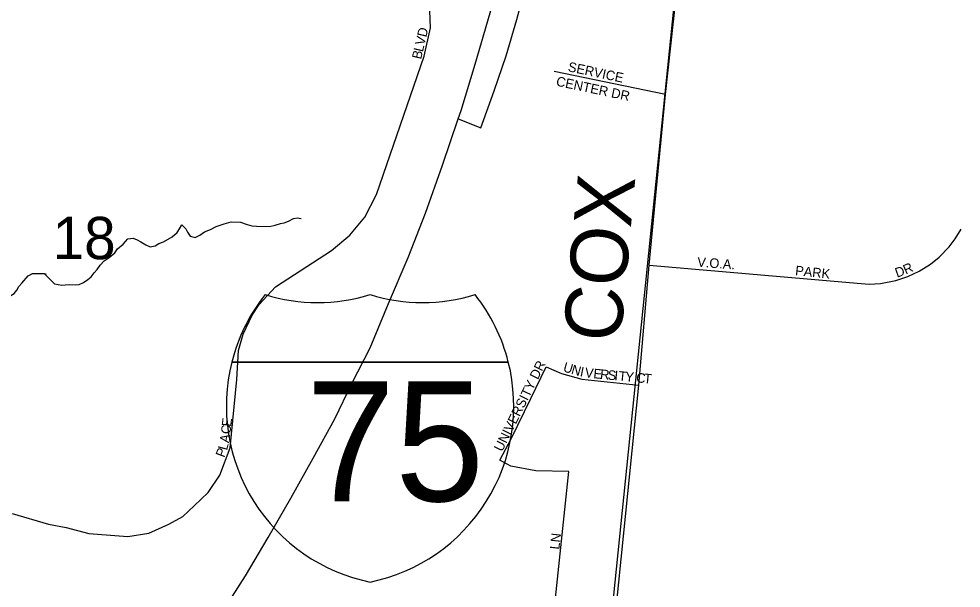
# Model space of a CAD drawing. Extents: x 1310247 to 1552180, y 377264 to 706493.
# Drawn here: x 1438264 to 1443181, y 499758 to 502730 of the extents above; entities that cross this region are included whole.
import ezdxf

# ---------------------------------------------------------------- set-up
doc = ezdxf.new("R2010")
doc.units = 0
for name, color, linetype in [('GM_X_County_Road', 7, 'Continuous'), ('GM_X_County_Road_Text', 7, 'Continuous'), ('GM_X_Interchange_Ramps', 7, 'Continuous'), ('GM_X_Interstate_Location', 7, 'Continuous'), ('GM_X_Interstate_Route', 7, 'Continuous'), ('GM_X_Interstate_Shield', 7, 'Continuous'), ('GM_X_Minor_River', 7, 'Continuous'), ('GM_X_Section', 7, 'Continuous'), ('GM_X_Section_Text', 7, 'Continuous'), ('GM_X_Township_Subdivision', 7, 'Continuous'), ('GM_X_Township_Subdivision_Text', 7, 'Continuous')]:
    doc.layers.add(name, color=color, linetype=linetype)

msp = doc.modelspace()

# ---------------------------------------------------------------- linework, layer by layer
at = {"layer": 'GM_X_County_Road'}
msp.add_lwpolyline([(1441235.6, 498171.6), (1441372, 499567.7), (1441499, 500818), (1441553.3, 501444.8), (1441639, 502335.6), (1441722.7, 503113.9), (1441767.5, 503283.3), (1441837.8, 503408), (1442232.6, 503914.4)], dxfattribs=at)
at = {"layer": 'GM_X_Interchange_Ramps'}
msp.add_lwpolyline([(1440557.2, 502207.6), (1440675.2, 502160.7), (1440744.7, 502353.4), (1440807.2, 502537.4), (1440862.7, 502726.7), (1440914.8, 502922.8), (1440958.2, 503115.6), (1440984.3, 503245.8), (1441029.4, 503511.4), (1441132.1, 504136.9), (1441164.8, 504302.2), (1441235.8, 504468.4), (1441318.6, 504585.1), (1441427, 504692.8), (1441529.4, 504767.5), (1441616.6, 504826.1), (1441646.1, 504844.3), (1441789.4, 504932.8), (1441766.8, 504966.7)], dxfattribs=at)
at = {"layer": 'GM_X_Interstate_Route'}
msp.add_lwpolyline([(1439292, 499579.6), (1439299.5, 499591.6), (1439446.8, 499823.6), (1439564.6, 500022), (1439682.5, 500228.5), (1439800.4, 500436.9), (1439912.2, 500641.5), (1440001.6, 500826.3), (1440097.2, 501013.1), (1440193.4, 501244), (1440295.9, 501484.9), (1440386.1, 501715.9), (1440474.7, 501966.9), (1440557.2, 502207.6), (1440572, 502252), (1440645.5, 502492.7), (1440723.5, 502761.1), (1440789.5, 503000.1), (1440858.7, 503283.7), (1440908.5, 503499.4), (1440969.5, 503775.1), (1441031.1, 504145.5), (1441038.8, 504195)], dxfattribs=at)
at = {"layer": 'GM_X_Interstate_Shield'}
for p, q in [((1439375.3, 500938.7), (1440818.1, 500938.7)), ((1440818.1, 500938.7), (1439375.3, 500938.7)), ((1440818.1, 500938.7), (1439375.3, 500938.7))]:
    msp.add_line(p, q, dxfattribs=at)
for centre, start, end in [((1440284.2, 500708.9), 141.669, 165.8066), ((1439822.8, 502186.9), 253.0091, 286.9909), ((1440370.7, 502186.9), 253.0091, 286.9909), ((1439909.2, 500708.9), 14.1934, 38.331), ((1440284.2, 500708.9), 165.8066, 258.463), ((1439909.2, 500708.9), 281.537, 14.1934)]:
    msp.add_arc(centre, 937.5, start, end, dxfattribs=at)
at = {"layer": 'GM_X_Minor_River'}
for points in [[(1438395.8, 501400.4), (1438450.4, 501346.5), (1438488.3, 501339.3), (1438506.4, 501340.8), (1438526.6, 501344.2), (1438560.6, 501341.1), (1438578.7, 501342.6), (1438601.1, 501354), (1438623.6, 501369.3), (1438642.1, 501382.8), (1438656.8, 501404.4), (1438673.4, 501422), (1438688, 501443.6), (1438708.8, 501467.1), (1438735.4, 501484.3), (1438764.2, 501509.5), (1438778.9, 501529.1), (1438807.7, 501554.4), (1438832.6, 501581.7), (1438860.8, 501584.8), (1438880.6, 501576.2), (1438900.4, 501565.6), (1438926, 501550.7), (1438949.8, 501540), (1438976, 501545.2), (1438994.4, 501556.7), (1439018.8, 501566), (1439063.7, 501592.7), (1439090.4, 501614), (1439103, 501633.6), (1439113.7, 501655.4), (1439135.2, 501634.7), (1439144.7, 501616.3), (1439158.1, 501595.8), (1439184, 501589), (1439208.4, 501600.3), (1439233, 501617.6), (1439263.5, 501630.8), (1439294.1, 501645.9), (1439334.6, 501660.7), (1439371, 501669.6), (1439421.1, 501668.1), (1439454.9, 501657), (1439478.8, 501650.2), (1439504.8, 501647.5), (1439571, 501645.4), (1439601.3, 501652.5), (1439629.7, 501661.7), (1439647.8, 501665.2), (1439670.2, 501674.5), (1439696.7, 501687.8), (1439716.8, 501691.1), (1439736.8, 501688.5)], [(1438006.4, 501193.5), (1438028.5, 501196.8), (1438054.9, 501206.1), (1438073.1, 501209.5), (1438103.5, 501220.6), (1438125.7, 501226), (1438150.2, 501237.3), (1438187, 501260.2), (1438221.8, 501285.3), (1438240.2, 501296.7), (1438252.8, 501314.4), (1438263.3, 501332.2), (1438279.9, 501349.7), (1438313.2, 501388.8), (1438335.6, 501400.2), (1438365.7, 501401.3), (1438395.8, 501400.4), (1438406.9, 501397.4)]]:
    msp.add_lwpolyline(points, dxfattribs=at)
at = {"layer": 'GM_X_Section'}
msp.add_lwpolyline([(1435955.9, 504591.9), (1441200.9, 504112.2), (1441809.7, 504059.9), (1441204.6, 498140.6), (1435471.2, 499726.6)], close=True, dxfattribs=at)
at = {"layer": 'GM_X_Township_Subdivision'}
for points in [[(1438228.2, 500148.4), (1438418.8, 500091.8), (1438511.6, 500074.6), (1438628.5, 500044.4), (1438833, 500028.4), (1438941.6, 500046.1), (1439047.2, 500092.3), (1439119.2, 500133), (1439178.3, 500188.2), (1439251.8, 500257.3), (1439312.5, 500348.1), (1439367.1, 500491.6), (1439402, 500846.9), (1439410.2, 500998.2), (1439434, 501083.5), (1439481, 501183), (1439517.7, 501238.3), (1439604, 501331.6), (1439894.9, 501520.9), (1439990.9, 501600.1), (1440070, 501695.4), (1440130.8, 501812.5), (1440378.5, 502534.6), (1440412.1, 502682.2), (1440406.1, 502816.3)], [(1441639, 502335.6), (1441056.8, 502455.1)], [(1441553.3, 501444.8), (1442659.7, 501348), (1442701.1, 501345.5), (1442760.5, 501349.3), (1442839.8, 501363.4), (1442902.1, 501385.1), (1442962.4, 501413.4), (1443020.9, 501449.3), (1443066.2, 501486.1), (1443118.1, 501539.9), (1443149.2, 501581.4), (1443181, 501632)], [(1440774.3, 500425.7), (1440835.4, 500542.1), (1440936.4, 500747.7), (1441016.3, 500914)], [(1441016.3, 500914), (1441096.2, 500878.8), (1441201.7, 500850), (1441499, 500818)], [(1440741.8, 498284.7), (1440899.1, 498753.2), (1440995.1, 499066.9), (1441053.2, 499606.5), (1441134.6, 500367.2), (1440961.9, 500370.4), (1440830.9, 500396), (1440774.3, 500425.7)]]:
    msp.add_lwpolyline(points, dxfattribs=at)

# ---------------------------------------------------------------- texts
at = {"layer": 'GM_X_County_Road_Text'}
msp.add_text('COX', height=300, rotation=84.8051, dxfattribs=at).set_placement((1441402.6, 501035.9))
at = {"layer": 'GM_X_Interstate_Location'}
for s in ['-', '.', ',']:
    msp.add_text(s, height=1, dxfattribs=at).set_placement((1440096.6, 500539.8))
msp.add_text('75', height=1, rotation=0, dxfattribs=at).set_placement((1439892.3, 500332.8))
at = {"layer": 'GM_X_Interstate_Shield'}
msp.add_text('75', height=625, dxfattribs=at).set_placement((1439762.7, 500212.2))
at = {"layer": 'GM_X_Section_Text'}
msp.add_text('18', height=221, rotation=0, dxfattribs=at).set_placement((1438440.3, 501475.6))
at = {"layer": 'GM_X_Township_Subdivision_Text'}
for s, rotation, p in [('D', 76.7759, (1440390, 502631.5)), ('V', 76.7581, (1440379.9, 502588.7)), ('L', 76.7556, (1440371.8, 502554.4)), ('B', 76.756, (1440362.8, 502515.9)), ('SERVICE', 348.1102, (1441126.2, 502456.9)), ('CENTER DR', 348.1122, (1441064.5, 502381.5)), ('V.O.A.', 355.8148, (1441802.6, 501436.3)), ('R', 24.0493, (1442891.9, 501394.9)), ('PARK', 353.9287, (1442313.3, 501392.3)), ('D', 19.3958, (1442846.3, 501378.7)), ('UNIVERSITY DR', 63.6774, (1440785.8, 500467.4)), ('U', 343.888, (1441100.6, 500890.3)), ('N', 343.896, (1441142.9, 500878.1)), ('I', 348.131, (1441189, 500865)), ('V', 353.4405, (1441215.6, 500859.6)), ('E', 354.5044, (1441260.3, 500854.5)), ('R', 354.5033, (1441295.3, 500851.1)), ('S', 354.5001, (1441334.7, 500847.3)), ('I', 354.483, (1441369.8, 500843.9)), ('T', 354.4971, (1441391.7, 500841.8)), ('Y', 354.4949, (1441426.7, 500838.5)), ('C', 354.4877, (1441483.6, 500833)), ('T', 354.4971, (1441523.1, 500829.2)), ('E', 83.4806, (1439371.8, 500599.6)), ('C', 83.4806, (1439367.3, 500560.3)), ('A', 80.7004, (1439359.8, 500514.2)), ('P', 69.5797, (1439335.8, 500437)), ('L', 75.1401, (1439349.7, 500475)), ('LN', 83.994, (1441084.2, 499958.3))]:
    msp.add_text(s, height=50, rotation=rotation, dxfattribs=at).set_placement(p)

doc.saveas('drawing.dxf')
